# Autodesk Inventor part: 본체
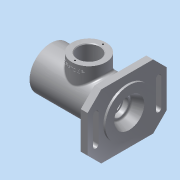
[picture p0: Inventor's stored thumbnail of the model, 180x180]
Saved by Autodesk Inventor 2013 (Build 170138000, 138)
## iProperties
Created: 2017-10
Part Number: 본체
Material: 알루미늄 6061
Document SubType Name: Modeling
Designer: Administrator
Density: 2.71 g/cm^3
Mass: 738.43 g
Surface Area: 652.241 cm^2
Volume: 272.484 cm^3
Author: Administrator
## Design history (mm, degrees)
sketch "스케치1"
  geometry: L1 (-58, 47)-(58, 47); L2 (58, 47)-(58, -47); L3 (58, -47)-(-58, -47); L4 (-58, -47)-(-58, 47); L5 (-50, 20)-(-50, -20); L6 (-42, -20)-(-42, 20); L7 (42, 20)-(42, -20); L8 (50, -20)-(50, 20); A1 r 4 centre (-46, -20) between (-50, -20) and (-42, -20); A2 r 4 centre (-46, 20) between (-42, 20) and (-50, 20); A3 r 4 centre (46, -20) between (42, -20) and (50, -20); A4 r 4 centre (46, 20) between (50, 20) and (42, 20); 5 further points
  constraints: 16 end point, 8 point on circle, 8 tangent, 5 horizontal alignment, 4 centre point, 4 midpoint, 4 vertical, 3 parallel, 1 equal radius, 1 horizontal, 1 perpendicular, 1 vertical alignment
  dimensions: "d0" = 116 distance of L1.start L1.end; "d2" = 94 distance of L1.end L2.end; "d3" = 46 horizontal distance of point (0, 0) A1.centre; "d4" = 46 horizontal distance of A3.centre point (0, 0); "d5" = 8 distance between parallel lines of L5 L6; "d6" = 40 distance of A1.centre A2.centre
extrude "돌출1" new body sketch "스케치1" distance "d7" = 10; taper "d8" = 0 deg
sketch "스케치2"
  geometry: C1 r 35 at (0, 0); 1 further point
  constraints: 1 centre point, 1 coincident
  dimensions: "d9" = 70 diameter of C1
extrude "돌출2" join sketch "스케치2" distance "d11" = 3; taper "d12" = 0 deg
sketch "스케치3"
  geometry: C1 r 31 at (0, 0); 1 further point
  constraints: 1 centre point, 1 coincident
  dimensions: "d13" = 62 diameter of C1
extrude "돌출3" join sketch "스케치3" distance "d14" = 102; taper "d15" = 0 deg
sketch "스케치4"
  geometry: L1 (-31, -102)-(31, -102) reference; C1 r 25 at (0, -46); 1 further point
  constraints: 1 centre point, 1 vertical alignment
  dimensions: "d16" = 56 distance from line of L1 C1.centre; "d17" = 50 diameter of C1
extrude "돌출4" join sketch "스케치4" distance "d18" = 47; taper "d19" = 0 deg
sketch "스케치5"
  geometry: L1 (35, 13)-(-35, 13) reference; L2 (-31, -102)-(31, -102) reference; L3 (0, 13)-(0, -102); L4 (16, -1)-(12.5, -1); L5 (12.5, -1)-(12.5, -8.3); L6 (12.5, -8.3)-(10, -8.3); L7 (10, -8.3)-(10, -11); L8 (10, -11)-(16.5, -11); L9 (16.5, -11)-(16.5, -16); L10 (16.5, -16)-(17.5, -16); L11 (17.5, -16)-(17.5, -27); L12 (17.5, -27)-(26, -27); L13 (26, -27)-(26, -65); L14 (26, -65)-(17.5, -65); L15 (17.5, -65)-(17.5, -76); L16 (17.5, -76)-(18.5, -76); L17 (18.5, -76)-(18.5, -77.75); L18 (18.5, -77.75)-(17.5, -77.75); L19 (17.5, -77.75)-(17.5, -81); L20 (17.5, -81)-(20, -81); L21 (20, -81)-(20, -90); L22 (20, -90)-(24, -90); L23 (24.101, -64.847)-(24, -64.847); L24 (24, -93)-(21, -93); L25 (21, -93)-(21, -102); L26 (16, -1)-(22, 13); L27 (24, -93)-(24, -90); 1 further point
  constraints: 50 end point, 10 horizontal, 10 vertical, 2 collinear, 2 midpoint, 2 point on line, 2 vertical alignment, 1 horizontal alignment, 1 perpendicular
  dimensions: "d21" = 52 diameter of L13 L3; "d24" = 32 diameter of L4.start L3; "d25" = 14 vertical distance of L4.start L26.end; "d26" = 25 diameter of L5 L3; "d27" = 20 diameter of L7 L3; "d28" = 33 diameter of L9 L3; "d29" = 35 diameter of L11 L3; "d30" = 37 diameter of L17 L3; "d31" = 40 diameter of L21 L3; "d32" = 48 diameter of L27 L3; "d33" = 42 diameter of L25 L3; "d35" = 2.7 distance of L6.end L7.end; "d36" = 5 distance of L8.end L9.end; "d40" = 3 distance of L24.start L22.end; "d43" = 1.75 distance of L16.end L17.end; "d61" = 44 diameter of L26.end L3; "d63" = 7.3 vertical distance of L4.start L5.end; "d96" = 12 distance from line of L22 L25.end; "d97" = 21 vertical distance of L25.end L20.end; "d98" = 26 distance from line of L25.end L16; "d99" = 38 distance of L12.end L13.end; "d100" = 11 distance of L10.end L11.end
revolve "회전1" sketch "스케치5" stored, may be unused: angle "d48" = 90 deg
hole "구멍1" diameter "d51" = 32; stored, may be unused: countersink angle "d55" = 90 deg, drill point angle "d57" = 118 deg; dims "d49" = 10, "d50" = 10, "d52" = 6, "d53" = 4, "d54" = 2, "d56" = 47
feature "스레드1" dims "d58" = 12, "d59" = 0
fillet "모깎기1" dims "d60" = 3
fillet "모깎기2" dims "d62" = 3
fillet "모깎기3" dims "d64" = 0.3
fillet "모깎기4" dims "d68" = 3
fillet "모깎기5" dims "d69" = 3
chamfer "모따기2" distance "d70" = 1; stored, may be unused: second distance "d71" = 2, angle "d72" = 30 deg
chamfer "모따기3" distance "d73" = 1; stored, may be unused: second distance "d74" = 2, angle "d75" = 30 deg
chamfer "모따기4" distance "d76" = 20; stored, may be unused: second distance "d77" = 2, angle "d78" = 30 deg
sketch "스케치6"
  geometry: L1 (0, -25)-(0, 25); L2 (31, 56)-(-31, 56) reference; 5 further points
  constraints: 2 end point, 2 horizontal alignment, 1 midpoint, 1 vertical, 1 vertical alignment, 3 other
  dimensions: "d79" = 56 distance from line of point (-20.5, 0) L2 (derived); "d80" = 20.5 distance of point (0, 0) point (-20.5, 0); "d81" = 20.5 distance of point (20.5, 0) point (0, 0)
hole "구멍2" sketch "스케치6" at (-20.5, 0), (20.5, 0) diameter "d82" = 2.459; stored, may be unused: countersink angle "d86" = 90 deg, drill point angle "d88" = 118 deg; dims "d83" = 6, "d84" = 4, "d85" = 2, "d87" = 8
fillet "모깎기6" dims "d95" = 3
node "작업 평면2"
sketch "스케치9"
  geometry: L1 (-47, -21)-(-47, -71) reference; L2 (-39, -44.77)-(-39, -47.23) reference; L3 (-22, -102)-(22, -102) reference; L4 (-34, -71)-(-47, -71) reference; 2 further points
  constraints: 1 other
  dimensions: "d104" = 56 distance from line of L3 point (-39, -46); "d105" = 8 distance from line of point (-39, -46) L1
feature "엠보싱2" sketch "스케치9" dims "d0" = 116, "d2" = 94, "d106" = 0.5, "d107" = 0
chamfer "모따기5" distance "d108" = 0.7; stored, may be unused: second distance "d109" = 2, angle "d110" = 30 deg
node "솔리드1"
other parameters: "d101" = -25
